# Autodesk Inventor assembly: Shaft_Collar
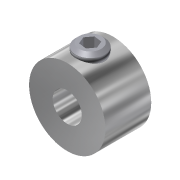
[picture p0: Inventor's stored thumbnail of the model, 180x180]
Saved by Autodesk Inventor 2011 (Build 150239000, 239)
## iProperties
Created: 2008-04
Part Number: Shaft_Collar
Document SubType Name: Assembly
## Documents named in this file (3)
- C:\Data Folder\VEX 2011\Inventor Datasets\Unit 7\Components\Shaft_Collar.iam
- C:\Data Folder\VEX 2011\Inventor Datasets\Unit 7\Components\SHAFT-COLLAR.ipt
- C:\Data Folder\VEX 2011\Inventor Datasets\Unit 7\Components\ANSI B18.3 - 8-32 UNC - 0.19(24).ipt
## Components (2 placed, 2 different names)
1. SHAFT-COLLAR:1 — Mate:1
2. Hexagon Socket Set Screw - Flat Point - Inch 8-32 UNC x 0.19:1 — Mate:1
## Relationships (1: Mate 1)
- Mate:1: SHAFT-COLLAR:1 ↔ Hexagon Socket Set Screw - Flat Point - Inch 8-32 UNC x 0.19:1
